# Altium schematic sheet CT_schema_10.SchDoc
size 387 x 278 mm
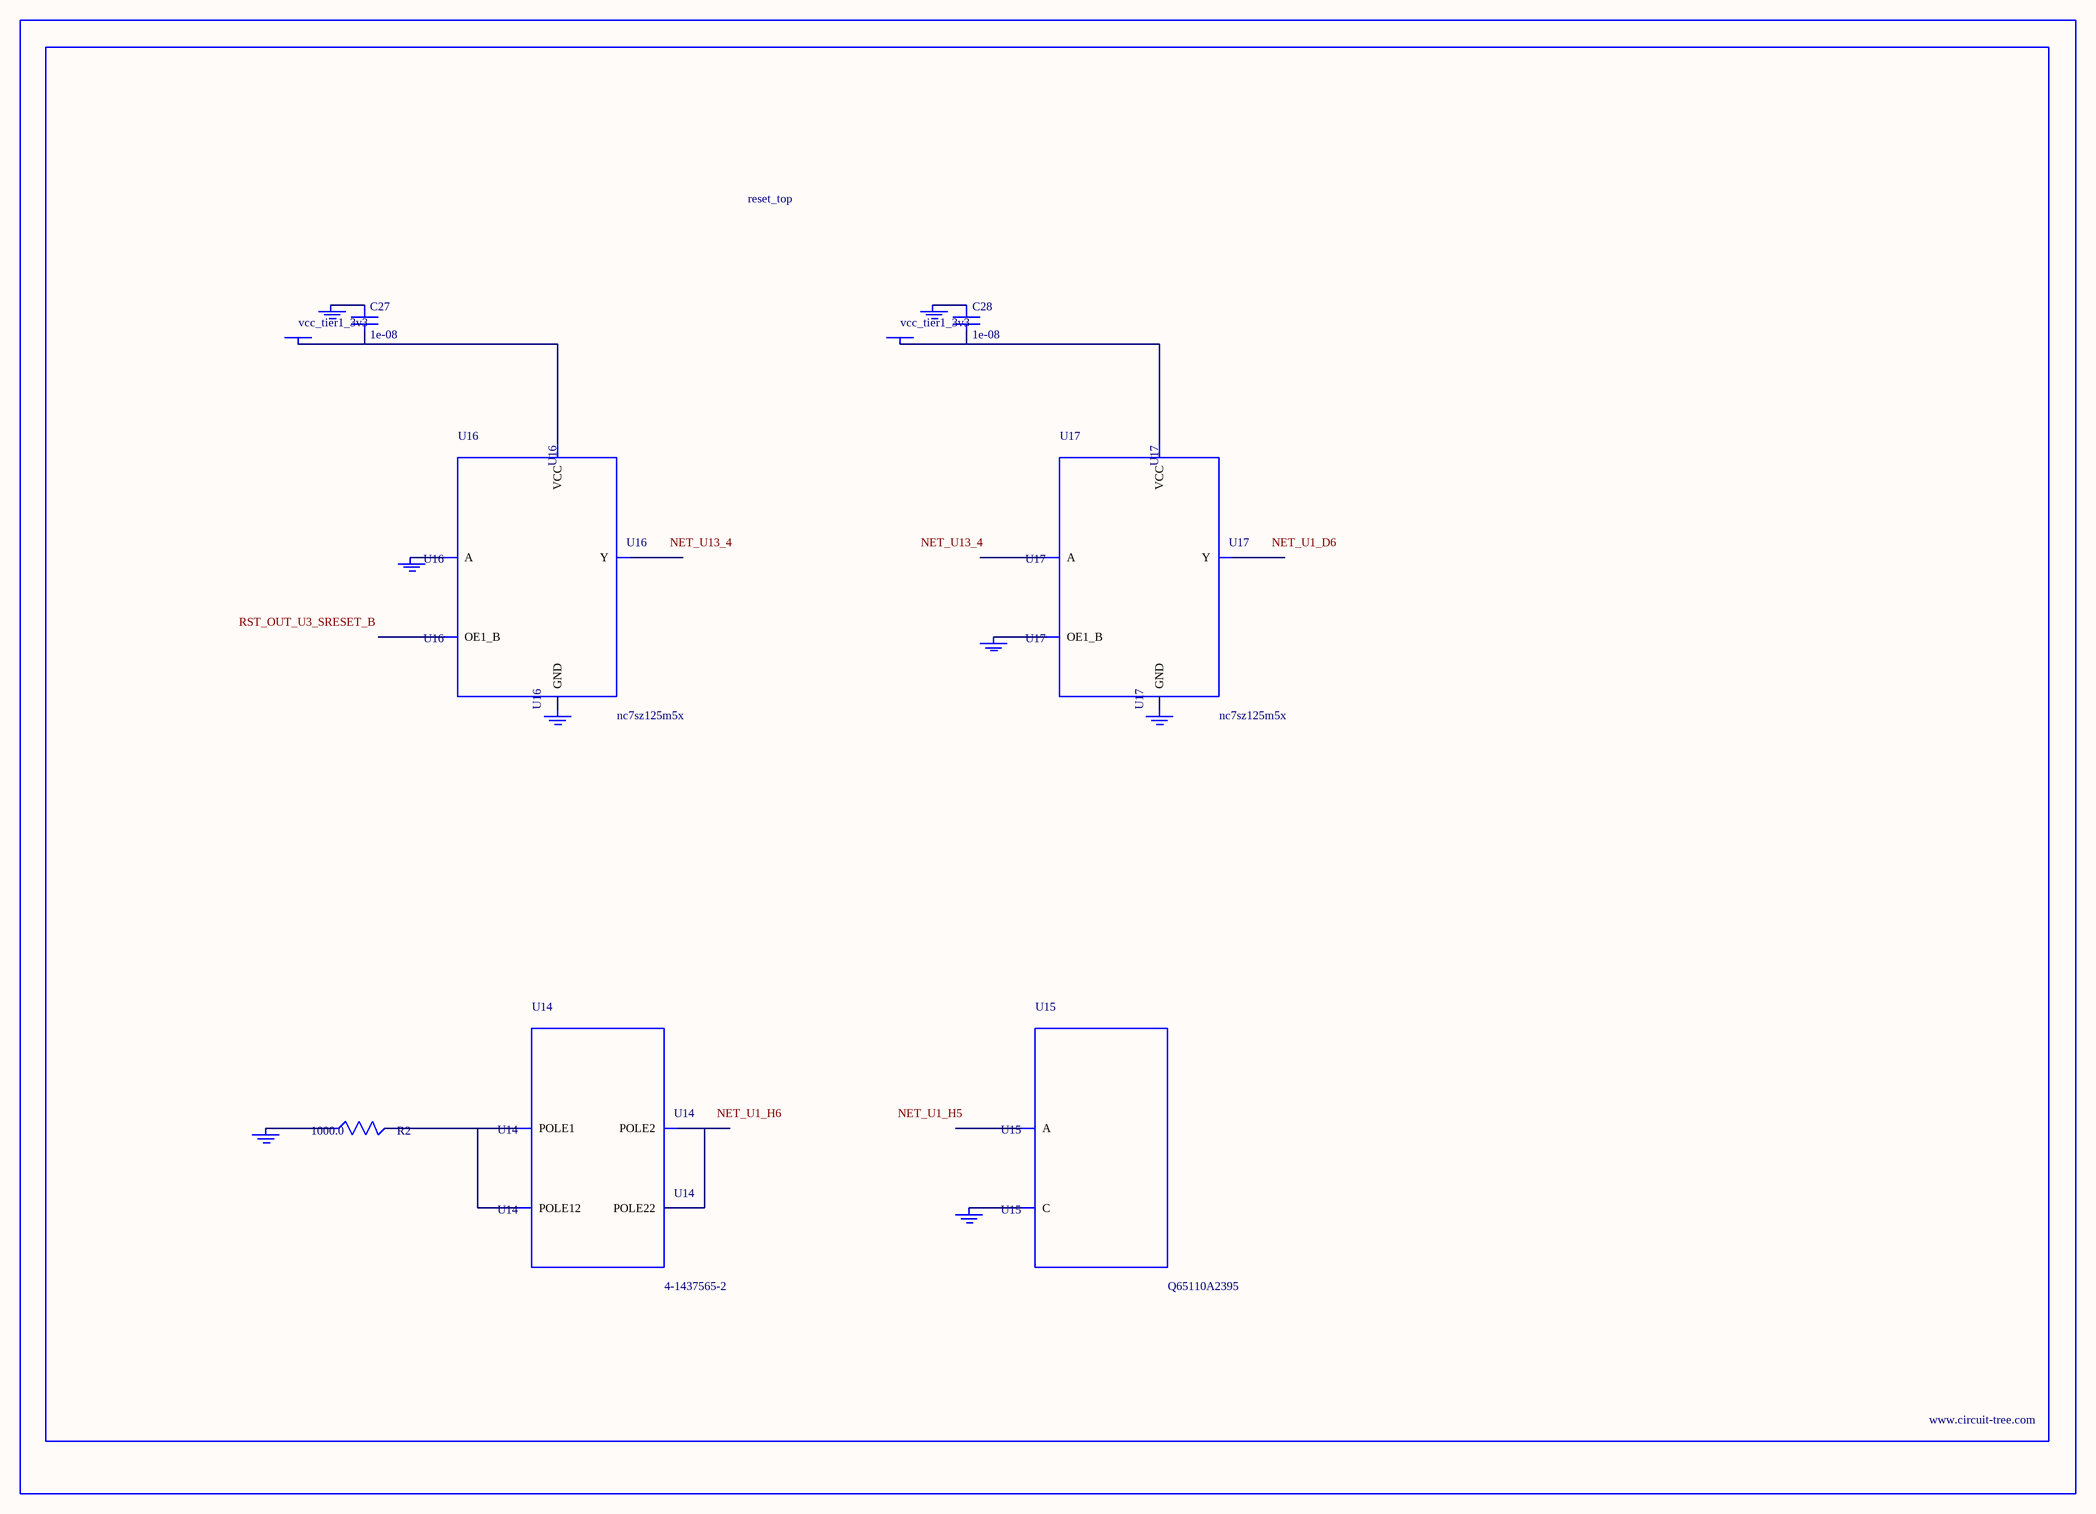
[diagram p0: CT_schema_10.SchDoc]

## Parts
BORDER9  (no value)
C27  1e-08  [C0402]
C28  1e-08  [C0402]
GND_INSTANCE_9_0  (no value)
GND_INSTANCE_9_1  (no value)
GND_INSTANCE_9_2  (no value)
GND_INSTANCE_9_3  (no value)
GND_INSTANCE_9_4  (no value)
GND_INSTANCE_9_5  (no value)
GND_INSTANCE_9_6  (no value)
GND_INSTANCE_9_7  (no value)
POWER_INSTANCE_9_0  vcc_tier1_3v3
POWER_INSTANCE_9_1  vcc_tier1_3v3
R2  1000.0  [R0603]
U14  4-1437565-2  [SW_4-1437565-2]
U15  Q65110A2395  [LGM67K-G1J2-24-Z]
U16  nc7sz125m5x  [NC7SZ125M5X]
U17  nc7sz125m5x  [NC7SZ125M5X]

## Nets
NetC27_1: C27.1 GND_INSTANCE_9_2.0(GND)
NetC27_2: C27.2 POWER_INSTANCE_9_0.0(PWR) U16.5(VCC)
NetC28_1: C28.1 GND_INSTANCE_9_5.0(GND)
NetC28_2: C28.2 POWER_INSTANCE_9_1.0(PWR) U17.5(VCC)
NetGND_INSTANCE_9_0_0: GND_INSTANCE_9_0.0(GND) R2.1
NetGND_INSTANCE_9_1_0: GND_INSTANCE_9_1.0(GND) U15.C
NetGND_INSTANCE_9_3_0: GND_INSTANCE_9_3.0(GND) U16.2(A)
NetGND_INSTANCE_9_4_0: GND_INSTANCE_9_4.0(GND) U16.3(GND)
NetGND_INSTANCE_9_6_0: GND_INSTANCE_9_6.0(GND) U17.1(OE1_B)
NetGND_INSTANCE_9_7_0: GND_INSTANCE_9_7.0(GND) U17.3(GND)
NetR2_2: R2.2 U14.1(POLE1) U14.2(POLE12)
NetU14_3: U14.3(POLE2) U14.4(POLE22)

Not connected (* = marked no-connect by the designer): U15 A; U16 1(OE1_B) 4(Y); U17 2(A) 4(Y)

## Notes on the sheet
- Labels drawn without touching a wire or pin: NET_U1_D6, NET_U1_H5, NET_U1_H6, NET_U13_4, RST_OUT_U3_SRESET_B

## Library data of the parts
BORDER9 = BORDER_PAGE9
C27 C28 = C0402C103K3RAC
GND_INSTANCE_9_0-GND_INSTANCE_9_7 = GND
POWER_INSTANCE_9_0 POWER_INSTANCE_9_1 = PWR
R2 = RC0603JR-071KL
